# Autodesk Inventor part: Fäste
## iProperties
Shininess: 64.0
Length Units: 11269
Angle Units: 11279
Time Units: 11290
Mass Units: 11283
Length Display Precision: 3
Angle Display Precision: 2
Compacted: True
Created: 2001-12
Part Number: Fäste
Material: S235JRG2
Document SubType Name: Modeling
Designer: Tobben
Density: 1 g/cm^3
Density: 0.0
Volumn: 0.0
Area: 0.0
PropertySet Name: Model Information
Control State: 0
Master: False
Checked Out: False
Author: Tobben
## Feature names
1. Extrusion1
2. Extrusion2
3. Extrusion3
4. Extrusion4
5. Hole1
6. Hole2
